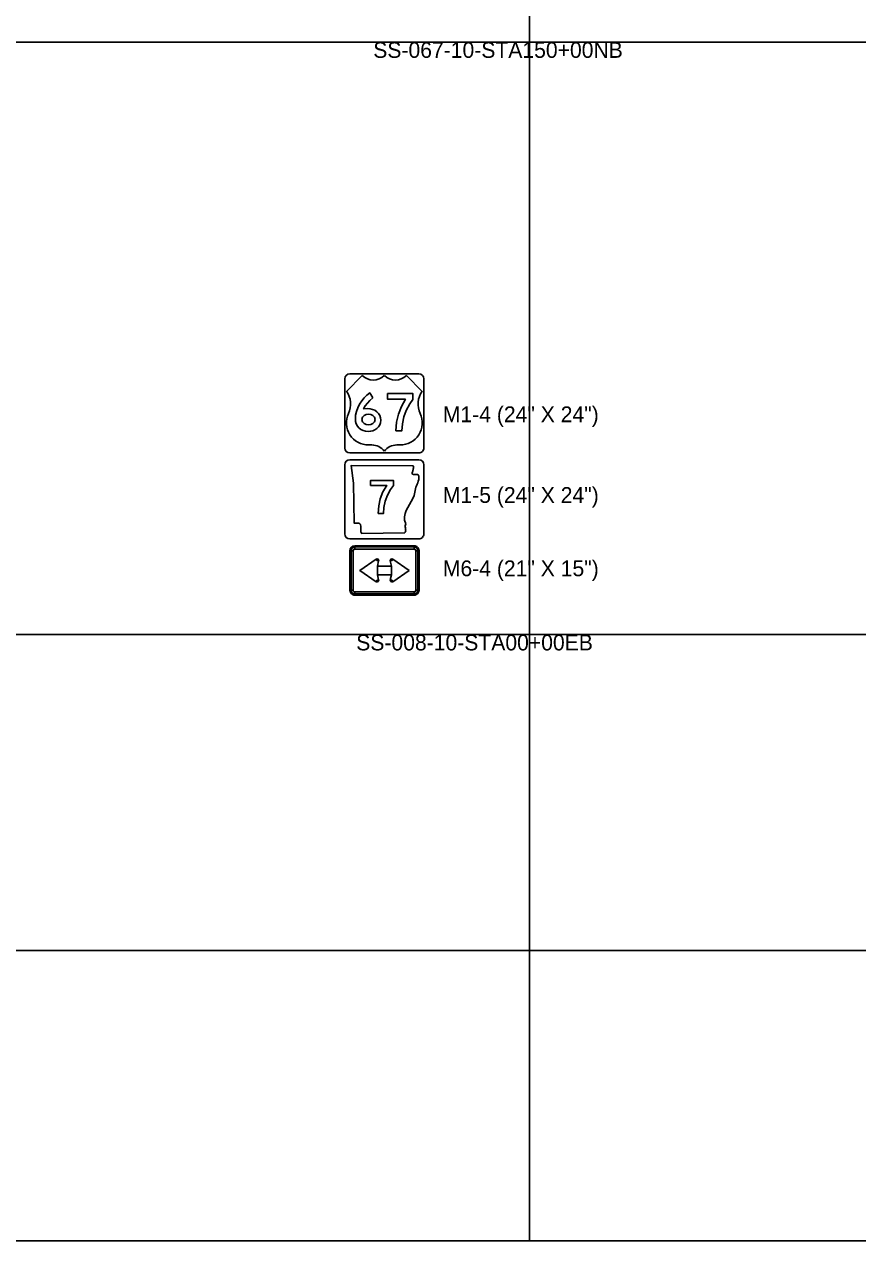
# Model space of a CAD drawing. Extents: x 1001568 to 1002149, y 1840825 to 1841423.
# Drawn here: x 1001907.86 to 1001928.96, y 1841148.13 to 1841178.92 of the extents above; entities that cross this region are included whole.
import ezdxf

# ---------------------------------------------------------------- set-up
doc = ezdxf.new("R2010")
doc.units = 0
for name, color, linetype in [('40', 7, 'Continuous'), ('R_No Plot', 7, 'Continuous'), ('SIGNS', 7, 'Continuous')]:
    doc.layers.add(name, color=color, linetype=linetype)

msp = doc.modelspace()

# ---------------------------------------------------------------- linework, layer by layer
at = {"layer": 'R_No Plot'}
for p, q in [((1001920.65, 1841210.667), (1001920.65, 1841148.127)), ((1001886.411, 1841178.469), (1001982.133, 1841178.469)), ((1001886.411, 1841163.469), (1001982.133, 1841163.469)), ((1001886.411, 1841155.469), (1001982.133, 1841155.469))]:
    msp.add_line(p, q, dxfattribs=at)
msp.add_lwpolyline([(1001886.411, 1841210.667), (1001964.232, 1841210.667), (1001964.232, 1841207.694), (1001968.454, 1841207.694), (1001968.454, 1841206.882), (1001982.133, 1841206.882), (1001982.133, 1841148.127), (1001886.411, 1841148.127)], close=True, dxfattribs=at)
at = {"layer": 'SIGNS'}
for p, q in [((1001915.977, 1841169.943), (1001915.977, 1841168.193)), ((1001916.418, 1841170.027), (1001916.019, 1841169.627)), ((1001917.852, 1841170.068), (1001916.102, 1841170.068)), ((1001917.936, 1841169.627), (1001917.536, 1841170.027)), ((1001917.977, 1841168.193), (1001917.977, 1841169.943)), ((1001915.977, 1841168.193), (1001915.977, 1841168.193)), ((1001916.578, 1841168.27), (1001916.658, 1841168.27)), ((1001917.297, 1841168.27), (1001917.377, 1841168.27)), ((1001916.102, 1841168.068), (1001917.852, 1841168.068)), ((1001917.852, 1841167.893), (1001916.102, 1841167.893)), ((1001915.977, 1841167.768), (1001915.977, 1841166.018)), ((1001917.977, 1841166.018), (1001917.977, 1841167.768)), ((1001915.977, 1841166.018), (1001915.977, 1841166.018)), ((1001916.102, 1841165.893), (1001917.852, 1841165.893)), ((1001917.731, 1841165.719), (1001916.231, 1841165.719)), ((1001916.231, 1841165.636), (1001916.231, 1841165.688)), ((1001917.731, 1841165.688), (1001917.731, 1841165.636)), ((1001916.106, 1841165.594), (1001916.106, 1841164.594)), ((1001916.138, 1841165.594), (1001916.19, 1841165.594)), ((1001916.772, 1841165.379), (1001916.794, 1841165.344)), ((1001916.794, 1841165.344), (1001916.834, 1841165.335)), ((1001917.128, 1841165.335), (1001917.169, 1841165.344)), ((1001917.169, 1841165.344), (1001917.191, 1841165.379)), ((1001917.773, 1841165.594), (1001917.825, 1841165.594)), ((1001917.856, 1841164.594), (1001917.856, 1841165.594)), ((1001916.794, 1841164.844), (1001916.772, 1841164.809)), ((1001916.834, 1841164.853), (1001916.794, 1841164.844)), ((1001917.169, 1841164.844), (1001917.128, 1841164.853)), ((1001917.191, 1841164.809), (1001917.169, 1841164.844)), ((1001916.19, 1841164.594), (1001916.138, 1841164.594)), ((1001916.231, 1841164.5), (1001916.231, 1841164.552)), ((1001916.231, 1841164.469), (1001917.731, 1841164.469)), ((1001917.731, 1841164.552), (1001917.731, 1841164.5)), ((1001917.825, 1841164.594), (1001917.773, 1841164.594))]:
    msp.add_line(p, q, dxfattribs=at)
for points in [[(1001915.977, 1841169.943), (1001915.977, 1841169.943)], [(1001916.102, 1841170.068), (1001916.102, 1841170.068)], [(1001917.852, 1841170.068), (1001917.852, 1841170.068)], [(1001916.686, 1841169.463), (1001916.61, 1841169.588), (1001916.535, 1841169.532), (1001916.467, 1841169.466), (1001916.405, 1841169.389), (1001916.349, 1841169.301), (1001916.303, 1841169.207), (1001916.271, 1841169.114), (1001916.251, 1841169.022), (1001916.244, 1841168.931), (1001916.25, 1841168.863), (1001916.267, 1841168.802), (1001916.295, 1841168.748), (1001916.335, 1841168.7), (1001916.383, 1841168.661), (1001916.438, 1841168.633), (1001916.499, 1841168.616), (1001916.567, 1841168.611), (1001916.628, 1841168.615), (1001916.685, 1841168.63), (1001916.738, 1841168.654), (1001916.787, 1841168.688), (1001916.832, 1841168.731), (1001916.863, 1841168.78), (1001916.882, 1841168.834), (1001916.889, 1841168.894), (1001916.882, 1841168.957), (1001916.863, 1841169.015), (1001916.831, 1841169.067), (1001916.786, 1841169.112), (1001916.736, 1841169.147), (1001916.681, 1841169.171), (1001916.62, 1841169.186), (1001916.555, 1841169.191), (1001916.454, 1841169.181), (1001916.496, 1841169.258), (1001916.549, 1841169.331), (1001916.612, 1841169.399), (1001916.686, 1841169.463)], [(1001916.41, 1841168.916), (1001916.423, 1841168.972), (1001916.464, 1841169.018), (1001916.516, 1841169.044), (1001916.575, 1841169.053), (1001916.633, 1841169.044), (1001916.686, 1841169.018), (1001916.728, 1841168.972), (1001916.742, 1841168.916), (1001916.728, 1841168.858), (1001916.686, 1841168.812), (1001916.634, 1841168.785), (1001916.575, 1841168.777), (1001916.515, 1841168.785), (1001916.464, 1841168.812), (1001916.423, 1841168.858), (1001916.41, 1841168.916)], [(1001916.102, 1841168.068), (1001916.102, 1841168.068)], [(1001916.102, 1841167.893), (1001916.102, 1841167.893)], [(1001917.852, 1841168.068), (1001917.852, 1841168.068)], [(1001917.852, 1841167.893), (1001917.852, 1841167.893)], [(1001915.977, 1841167.768), (1001915.977, 1841167.768)], [(1001916.102, 1841165.893), (1001916.102, 1841165.893)], [(1001917.852, 1841165.893), (1001917.852, 1841165.893)]]:
    msp.add_lwpolyline(points, dxfattribs=at)
for points in [[(1001917.27, 1841168.629), (1001917.422, 1841168.629), (1001917.434, 1841168.806), (1001917.471, 1841168.979), (1001917.533, 1841169.146), (1001917.62, 1841169.31), (1001917.703, 1841169.422), (1001917.703, 1841169.569), (1001917.059, 1841169.569), (1001917.059, 1841169.428), (1001917.513, 1841169.428), (1001917.408, 1841169.244), (1001917.333, 1841169.05), (1001917.287, 1841168.845)], [(1001917.707, 1841167.738), (1001917.712, 1841167.719), (1001917.714, 1841167.7), (1001917.713, 1841167.681), (1001917.711, 1841167.662), (1001917.707, 1841167.643), (1001917.702, 1841167.624), (1001917.696, 1841167.605), (1001917.691, 1841167.586), (1001917.685, 1841167.568), (1001917.68, 1841167.55), (1001917.694, 1841167.534), (1001917.712, 1841167.524), (1001917.731, 1841167.52), (1001917.753, 1841167.52), (1001917.774, 1841167.521), (1001917.795, 1841167.521), (1001917.814, 1841167.519), (1001917.831, 1841167.513), (1001917.844, 1841167.501), (1001917.852, 1841167.48), (1001917.852, 1841167.435), (1001917.847, 1841167.392), (1001917.836, 1841167.352), (1001917.822, 1841167.313), (1001917.806, 1841167.275), (1001917.79, 1841167.237), (1001917.775, 1841167.199), (1001917.763, 1841167.159), (1001917.754, 1841167.118), (1001917.752, 1841167.074), (1001917.73, 1841166.991), (1001917.697, 1841166.913), (1001917.656, 1841166.838), (1001917.612, 1841166.763), (1001917.569, 1841166.688), (1001917.531, 1841166.612), (1001917.503, 1841166.534), (1001917.488, 1841166.451), (1001917.492, 1841166.364), (1001917.518, 1841166.27), (1001917.51, 1841166.247), (1001917.507, 1841166.223), (1001917.508, 1841166.199), (1001917.511, 1841166.175), (1001917.514, 1841166.151), (1001917.517, 1841166.128), (1001917.518, 1841166.104), (1001917.514, 1841166.083), (1001917.506, 1841166.061), (1001917.49, 1841166.042), (1001916.407, 1841166.032), (1001916.392, 1841166.052), (1001916.384, 1841166.075), (1001916.38, 1841166.102), (1001916.38, 1841166.13), (1001916.38, 1841166.16), (1001916.381, 1841166.189), (1001916.379, 1841166.218), (1001916.373, 1841166.245), (1001916.362, 1841166.269), (1001916.344, 1841166.29), (1001916.217, 1841166.29), (1001916.199, 1841167.302), (1001916.136, 1841167.748), (1001917.707, 1841167.738), (1001917.707, 1841167.738)], [(1001916.82, 1841166.532), (1001916.956, 1841166.532), (1001916.967, 1841166.691), (1001917, 1841166.845), (1001917.055, 1841166.995), (1001917.133, 1841167.142), (1001917.208, 1841167.242), (1001917.208, 1841167.374), (1001916.631, 1841167.374), (1001916.631, 1841167.248), (1001917.037, 1841167.248), (1001916.943, 1841167.083), (1001916.876, 1841166.909), (1001916.835, 1841166.725)], [(1001917.731, 1841165.688), (1001916.231, 1841165.688), (1001916.231, 1841165.636), (1001917.731, 1841165.636), (1001917.731, 1841165.688), (1001917.731, 1841165.688)], [(1001916.138, 1841165.594), (1001916.138, 1841164.594), (1001916.19, 1841164.594), (1001916.19, 1841165.594), (1001916.138, 1841165.594), (1001916.138, 1841165.594)], [(1001916.356, 1841165.094), (1001916.772, 1841164.809), (1001916.794, 1841164.844), (1001916.834, 1841164.853), (1001916.804, 1841164.985), (1001916.804, 1841165.203), (1001916.834, 1841165.335), (1001916.794, 1841165.344), (1001916.772, 1841165.379), (1001916.356, 1841165.094), (1001916.356, 1841165.094)], [(1001917.606, 1841165.094), (1001917.191, 1841165.379), (1001917.169, 1841165.344), (1001917.128, 1841165.335), (1001917.158, 1841165.203), (1001917.158, 1841164.985), (1001917.128, 1841164.853), (1001917.169, 1841164.844), (1001917.191, 1841164.809), (1001917.606, 1841165.094), (1001917.606, 1841165.094)], [(1001917.825, 1841164.594), (1001917.825, 1841165.594), (1001917.773, 1841165.594), (1001917.773, 1841164.594), (1001917.825, 1841164.594), (1001917.825, 1841164.594)], [(1001917.158, 1841164.985), (1001917.158, 1841165.203), (1001916.804, 1841165.203), (1001916.804, 1841164.985), (1001917.158, 1841164.985), (1001917.158, 1841164.985)], [(1001916.231, 1841164.5), (1001917.731, 1841164.5), (1001917.731, 1841164.552), (1001916.231, 1841164.552), (1001916.231, 1841164.5), (1001916.231, 1841164.5)]]:
    msp.add_lwpolyline(points, close=True, dxfattribs=at)
for centre, radius, start, end in [((1001916.102, 1841169.943), 0.125, 90.0002, 179.9998), ((1001916.698, 1841170.312), 0.399, 225.5729, 314.4272), ((1001917.257, 1841170.312), 0.399, 225.5729, 314.4272), ((1001917.852, 1841169.943), 0.125, 360, 90), ((1001915.565, 1841169.302), 0.559, 334.9895, 35.6629), ((1001918.39, 1841169.302), 0.559, 144.3372, 205.01), ((1001916.578, 1841168.829), 0.559, 154.9897, 270.0001), ((1001917.377, 1841168.829), 0.559, 270.0001, 25.0104), ((1001916.102, 1841168.193), 0.125, 180, 270), ((1001916.658, 1841167.871), 0.399, 36.8699, 90.0002), ((1001917.297, 1841167.871), 0.399, 90.0002, 143.13), ((1001917.852, 1841168.193), 0.125, 270.0001, 0.0003), ((1001916.102, 1841167.768), 0.125, 90.0002, 179.9998), ((1001917.852, 1841167.768), 0.125, 360, 90), ((1001916.102, 1841166.018), 0.125, 180, 270), ((1001917.852, 1841166.018), 0.125, 270.0001, 0.0003), ((1001916.231, 1841165.594), 0.125, 90.0002, 179.9998), ((1001916.231, 1841165.594), 0.0937, 90.0002, 179.9998), ((1001916.231, 1841165.594), 0.0417, 90.0002, 179.9998), ((1001917.731, 1841165.594), 0.125, 360, 90.0002), ((1001917.731, 1841165.594), 0.0937, 360, 90.0002), ((1001917.731, 1841165.594), 0.0417, 360, 90.0002), ((1001916.794, 1841165.344), 0.0417, 347.0497, 122.2758), ((1001917.169, 1841165.344), 0.0417, 57.7244, 192.9504), ((1001916.794, 1841164.844), 0.0417, 237.7242, 12.9503), ((1001917.169, 1841164.844), 0.0417, 167.0499, 302.2759), ((1001916.231, 1841164.594), 0.125, 179.9998, 270.0001), ((1001916.231, 1841164.594), 0.0937, 179.9998, 270.0001), ((1001916.231, 1841164.594), 0.0417, 179.9998, 270.0001), ((1001917.731, 1841164.594), 0.125, 270.0001, 0.0003), ((1001917.731, 1841164.594), 0.0937, 270.0001, 0.0003), ((1001917.731, 1841164.594), 0.0417, 270.0001, 0.0003)]:
    msp.add_arc(centre, radius, start, end, dxfattribs=at)

# ---------------------------------------------------------------- texts
at = {"layer": '40'}
for s, p in [('SS-067-10-STA150+00NB', (1001916.697, 1841178.069)), ('M1-4 (24" X 24")', (1001918.459, 1841168.846)), ('M1-5 (24" X 24")', (1001918.459, 1841166.803)), ('M6-4 (21" X 15")', (1001918.459, 1841164.947)), ('SS-008-10-STA00+00EB', (1001916.266, 1841163.069))]:
    msp.add_text(s, height=0.4, rotation=0, dxfattribs=at).set_placement(p)

doc.saveas('drawing.dxf')
